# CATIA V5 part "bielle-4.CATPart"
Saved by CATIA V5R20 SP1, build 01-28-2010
Part number: bielle-4
Bounding box of the stored display mesh (mm): x -263.953 to 136.047, y -19.766 to 10.234, z 0 to 60
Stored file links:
  C:\Users\Manon\Desktop\IAO\Pieces\bielle-4.CATPart
  C:\Users\Manon\Desktop\IAO\assemblage\Assemblage_rlanglais.CATProduct
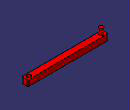
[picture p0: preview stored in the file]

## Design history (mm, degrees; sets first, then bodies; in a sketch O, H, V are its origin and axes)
External parameters (linked from other documents)
  External.bielle_4 = 360 mm
Body1 (main body)
  Sketch1 on xy-plane, origin (0, 0, 0), H (1, 0, 0), V (0, 1, 0)
    line L1 (-263.9533, 10.2345) -> (136.0467, 10.2345)
    line L2 (136.0467, 10.2345) -> (136.0467, -19.7655)
    line L3 (136.0467, -19.7655) -> (-263.9533, -19.7655)
    line L4 (-263.9533, -19.7655) -> (-263.9533, 10.2345)
    circle A1 centre (116.0467, -4.7655) radius 10
    point P5 (116.0467, -4.7655)
    point P6 (124.8381, 0)
    circle A2 centre (-243.9533, -4.7655) radius 10
    point P7 (-243.9533, -4.7655)
    length L2 = 30
    length L1 = 400
    radius A2 = 10
    radius A1 = 10
    distance P5 L2 = 20
    distance P5 L1 = 15
    distance P5 P7 = 360 {= External.bielle_4}
    distance P7 L3 = 15
    horizontal: L1 H, L3 H
    vertical: L2 V, L4 V
    coincidence: A1 P6, P6 H
  Pad1: profile Sketch1, direction (0, 0, 1), length 30
  Fillet1: radius 5, on edge [face of Pad1 from Sketch1.L1 | face of Pad1 from Sketch1.L2]; edge [face of Pad1 from Sketch1.L2 | face of Pad1 from Sketch1.L3]; edge [face of Pad1 from Sketch1.L4 | face of Pad1 from Sketch1.L1]; edge [face of Pad1 from Sketch1.L3 | face of Pad1 from Sketch1.L4]
  Sketch2 on end face of Pad1, origin (0, 0, 30), H (1, 0, 0), V (0, 1, 0)
    circle A1 centre (-243.9533, -4.7655) radius 10
    reference projected circle E1 centre (-243.9533, -4.7655) radius 10 from edge [face of Pad1 from Sketch1.A2 | start face of Pad1]
    coincidence: E1 A1
  Pad2: profile Sketch2, direction (0, 0, 1), length 30, mirrored extent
